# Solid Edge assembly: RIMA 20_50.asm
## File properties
Title: Zylinder
Author: ahadarics
Template: iso metric assembly.asm
Last saved by: ahadarics
Revision: 4
Application: Solid Edge
Username: ahadarics
Dokumentum tartalom típus: 1
Document Number: RIMA 20/50
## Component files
Profilrohr.par
Kolbenstange.par
Kit_1.par
Kit_2.par
Mutter_1.par
Mutter_2.par
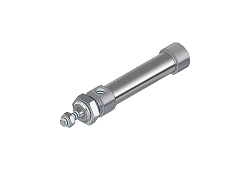
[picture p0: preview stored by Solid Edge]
